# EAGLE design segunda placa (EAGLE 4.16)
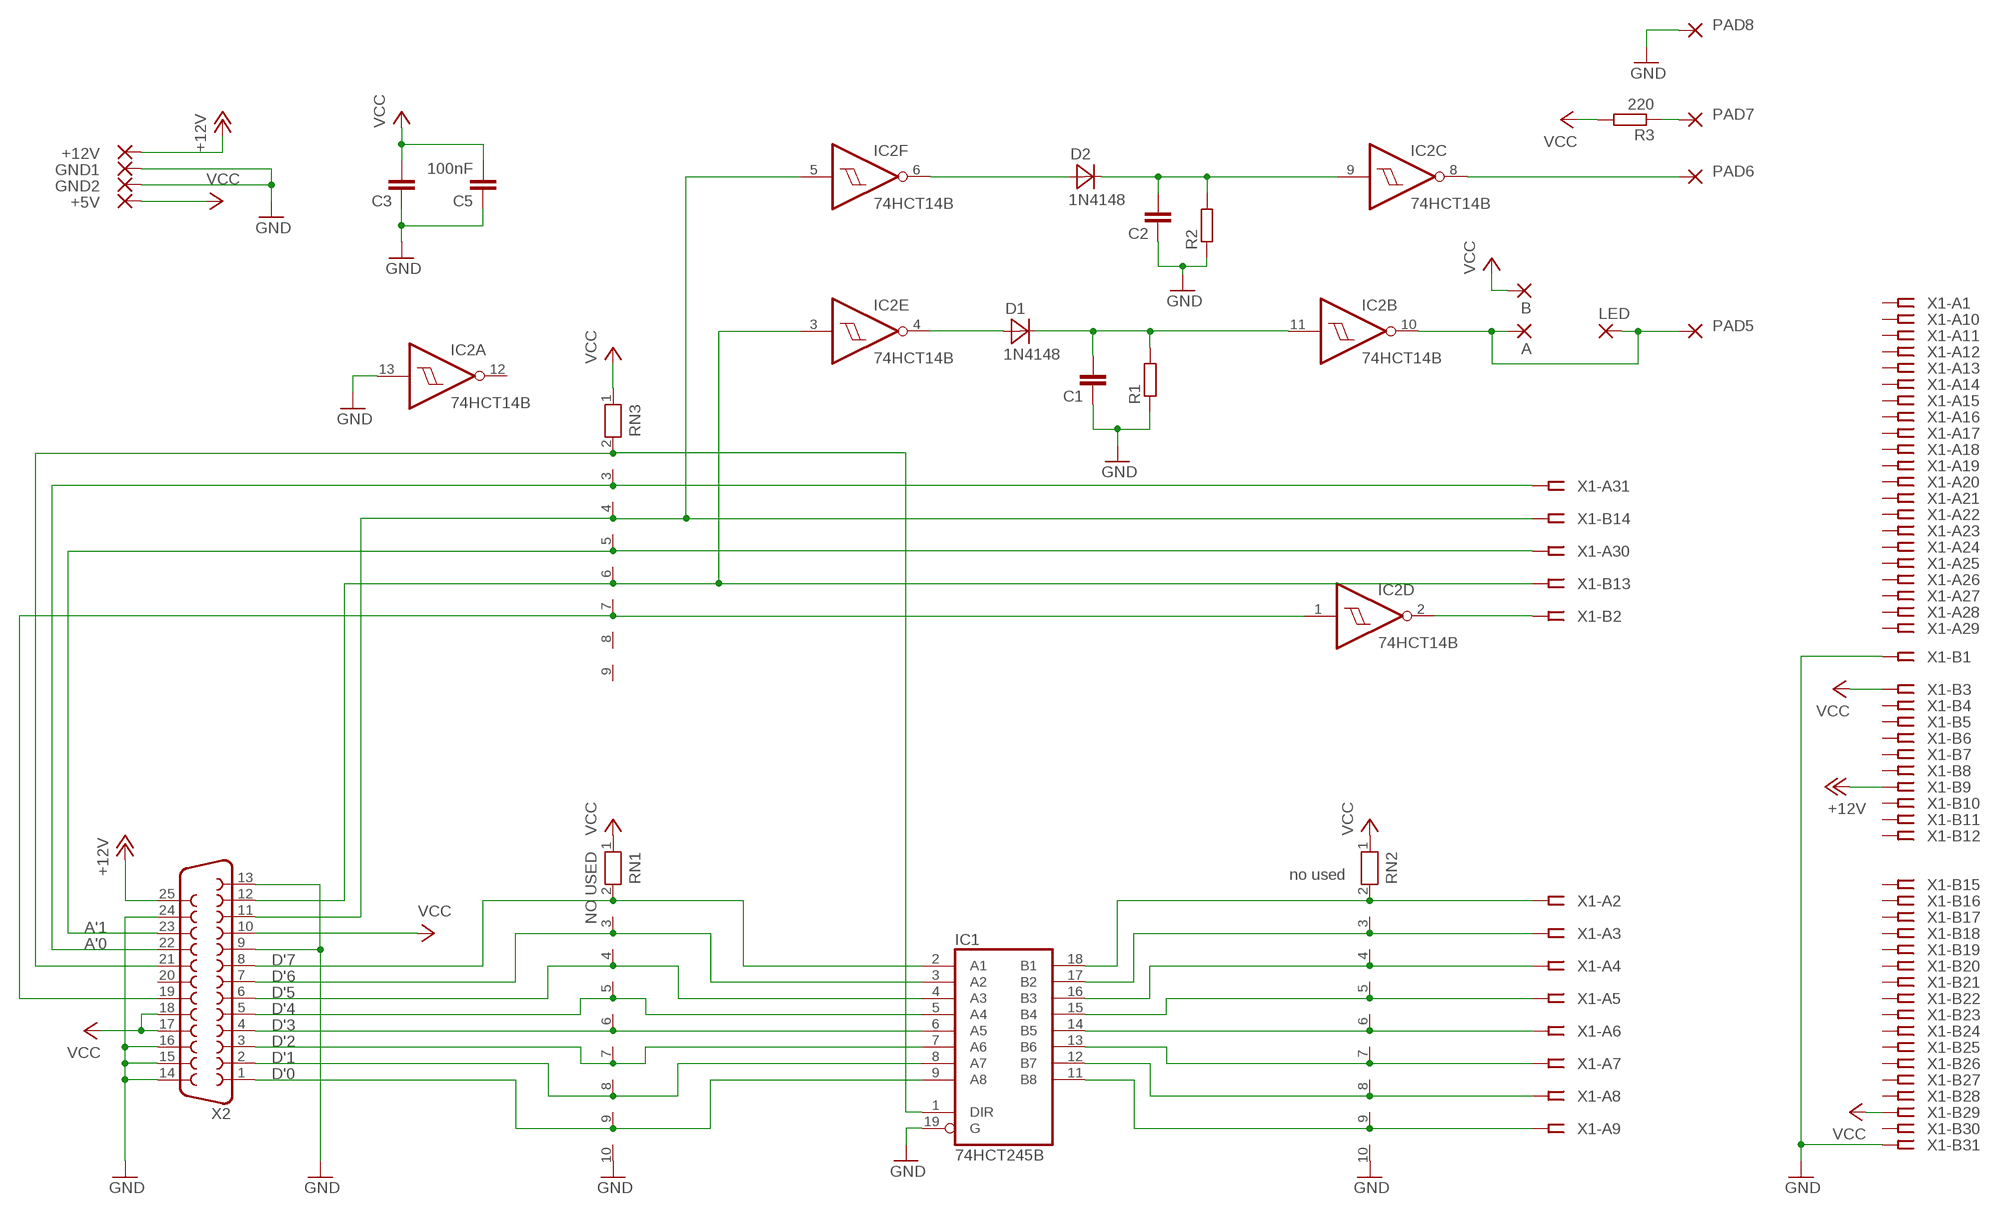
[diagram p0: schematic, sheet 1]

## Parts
+5V  1,6/0,9  [1,6/0,9]
+12V  1,6/0,9  [1,6/0,9]
A  SMD2  [SMD1,27-2,54]
B  SMD2  [SMD1,27-2,54]
C1  C-EU050-024X044  [C050-024X044]
C2  C-EU050-024X044  [C050-024X044]
C3  C-EU050-024X044  [C050-024X044]
C5  100nF  C-EU050-024X044  [C050-024X044]
D1  1N4148  DIODE-10/2  [D-10/2]
D2  1N4148  DIODE-10/2  [D-10/2]
GND1  1,6/0,9  [1,6/0,9]
GND2  1,6/0,9  [1,6/0,9]
IC1  74HCT245B  [DIL20-B]
IC2  74HCT14B  [DIL14-B]
LED  SMD2  [SMD1,27-2,54]
PAD5  1,6/0,9  [1,6/0,9]
PAD6  1,6/0,9  [1,6/0,9]
PAD7  1,6/0,9  [1,6/0,9]
PAD8  1,6/0,9  [1,6/0,9]
R1  R-EU_0207/10  [0207/10]
R2  R-EU_0207/10  [0207/10]
R3  220  R-EU_0207/10  [0207/10]
RN1  NO USED  RN091  [RN-101]
RN2  no used  RN091  [RN-101]
RN3  RN081  [RN-91]
X1  ISA-SLOT  [ISA-16]
X2  F25H  [F25H]

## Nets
+12V: +12V.1(P) X1.B9 X2.25
A'0: RN3.3 X1.A31 X2.22
A'1: RN3.5 X1.A30 X2.23
D'0: IC1.9(A8) RN1.9 X2.1
D'1: IC1.8(A7) RN1.8 X2.2
D'2: IC1.7(A6) RN1.7 X2.3
D'3: IC1.6(A5) RN1.6 X2.4
D'4: IC1.5(A4) RN1.5 X2.5
D'5: IC1.4(A3) RN1.4 X2.6
D'6: IC1.3(A2) RN1.3 X2.7
D'7: IC1.2(A1) RN1.2 X2.8
GND: C1.1 C2.1 C3.1 C5.1 GND1.1(P) GND2.1(P) IC1.19(G) IC2.13(A:I) PAD8.1(P) R1.1 R2.1 RN1.10 RN2.10 X1.B1 X1.B31 X2.9 X2.13 X2.14 X2.15 X2.16 X2.24
N$1: PAD7.1(P) R3.1
N$2: IC1.18(B1) RN2.2 X1.A2
N$3: IC1.17(B2) RN2.3 X1.A3
N$4: IC1.16(B3) RN2.4 X1.A4
N$5: IC1.15(B4) RN2.5 X1.A5
N$6: IC1.14(B5) RN2.6 X1.A6
N$7: IC1.13(B6) RN2.7 X1.A7
N$8: IC1.12(B7) RN2.8 X1.A8
N$9: IC1.11(B8) RN2.9 X1.A9
N$10: IC2.2(D:O) X1.B2
N$12: IC2.5(F:I) RN3.4 X1.B14 X2.11
N$13: IC2.1(D:I) RN3.7 X2.19
N$14: IC2.3(E:I) RN3.6 X1.B13 X2.12
N$16: IC1.1(DIR) RN3.2 X2.21
N$17: C2.2 D2.P$4(K) IC2.9(C:I) R2.2
N$18: C1.2 D1.P$4(K) IC2.11(B:I) R1.2
N$19: D1.P$3(A) IC2.4(E:O)
N$20: IC2.8(C:O) PAD6.1(P)
N$21: D2.P$3(A) IC2.6(F:O)
N$22: A.1(P) IC2.10(B:O) LED.1(P) PAD5.1(P)
VCC: +5V.1(P) B.1(P) C3.2 C5.2 R3.2 RN1.1 RN2.1 RN3.1 X1.B3 X1.B29 X2.10 X2.17 X2.18
Unconnected: IC2.12(A:O) RN3.8 RN3.9 X1.A1 X1.A10 X1.A11 X1.A12 X1.A13 X1.A14 X1.A15 X1.A16 X1.A17 X1.A18 X1.A19 X1.A20 X1.A21 X1.A22 X1.A23 X1.A24 X1.A25 X1.A26 X1.A27 X1.A28 X1.A29 X1.B4 X1.B5 X1.B6 X1.B7 X1.B8 X1.B10 X1.B11 X1.B12 X1.B15 X1.B16 X1.B17 X1.B18 X1.B19 X1.B20 X1.B21 X1.B22 X1.B23 X1.B24 X1.B25 X1.B26 X1.B27 X1.B28 X1.B30 X2.20

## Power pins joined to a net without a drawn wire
GND: IC1.10(GND) IC2.7(P:GND)
VCC: IC1.20(VCC) IC2.14(P:VCC)

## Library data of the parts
+5V +12V GND1 GND2 PAD5-PAD8 = wirepad:1,6/0,9: THROUGH-HOLE PAD
A B LED = wirepad:SMD2: SMD PAD
C1-C3 C5 = rcl:C-EU: CAPACITOR, European symbol
D1 D2 = discrete2:DIODE-10/2
IC1 = 74xx-eu2:74*245: Octal BUS TRANSCEIVER, 3-state
IC2 = 74xx-eu2:74*14: Hex schmitt trigger INVERTER
R1-R3 = rcl:R-EU_: RESISTOR, European symbol
RN1 RN2 = discrete2:RN09
RN3 = discrete2:RN08
X1 = con-pc2:ISA-SLOT: ISA SLOT
X2 = con-subd:F25: SUB-D

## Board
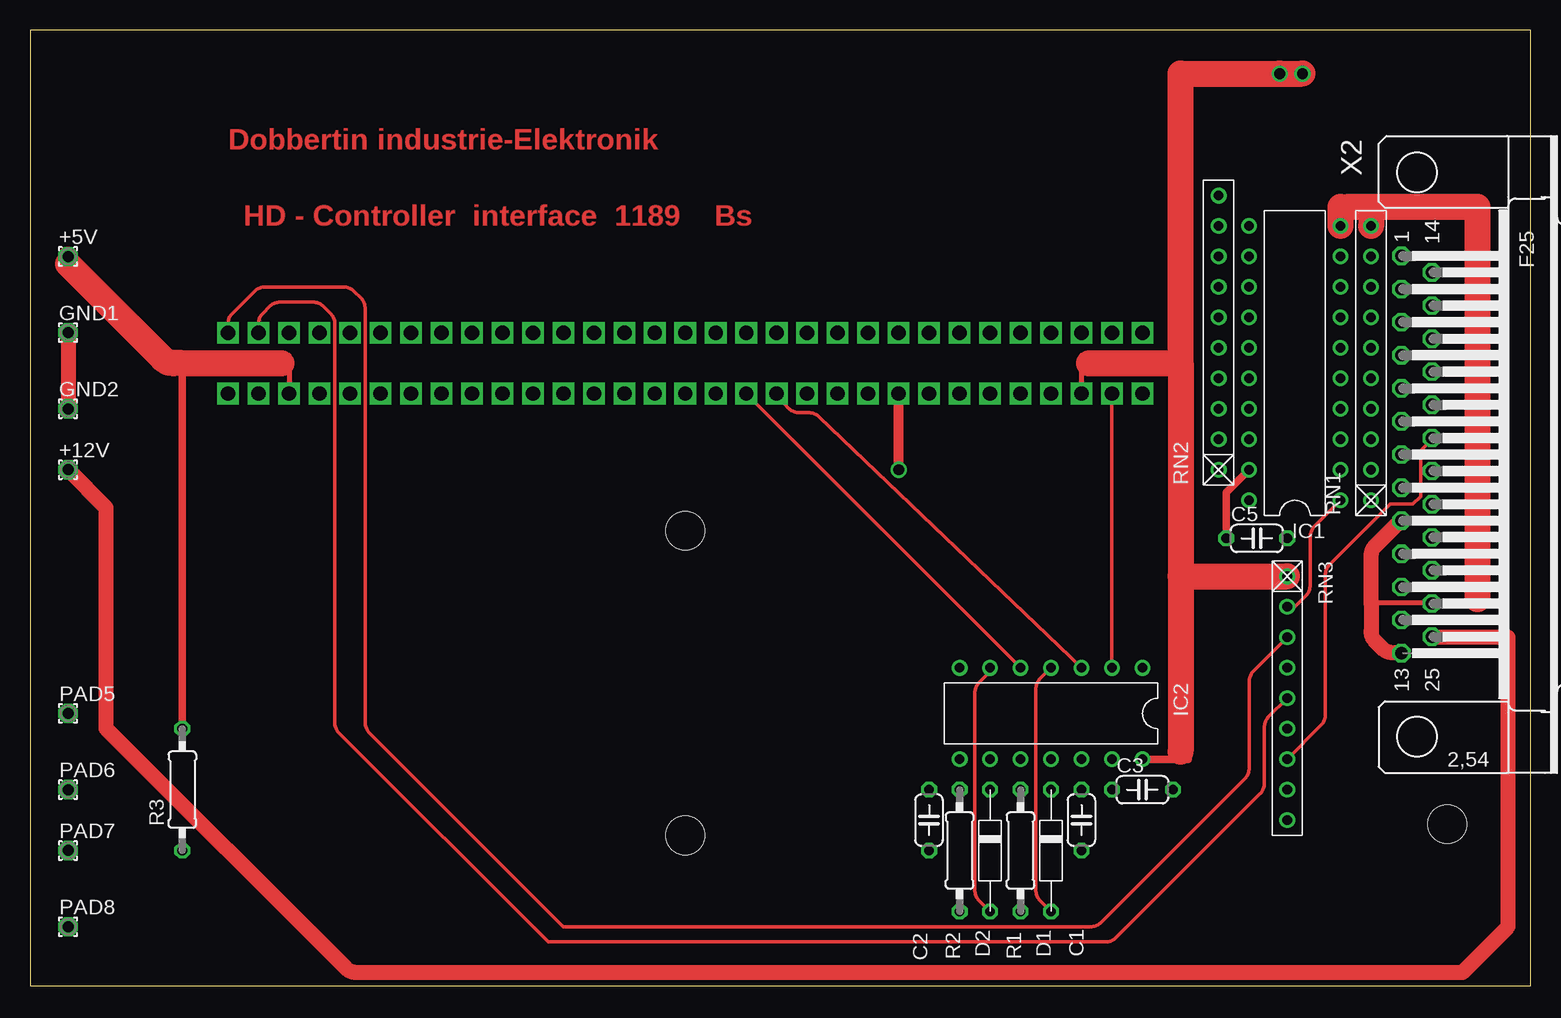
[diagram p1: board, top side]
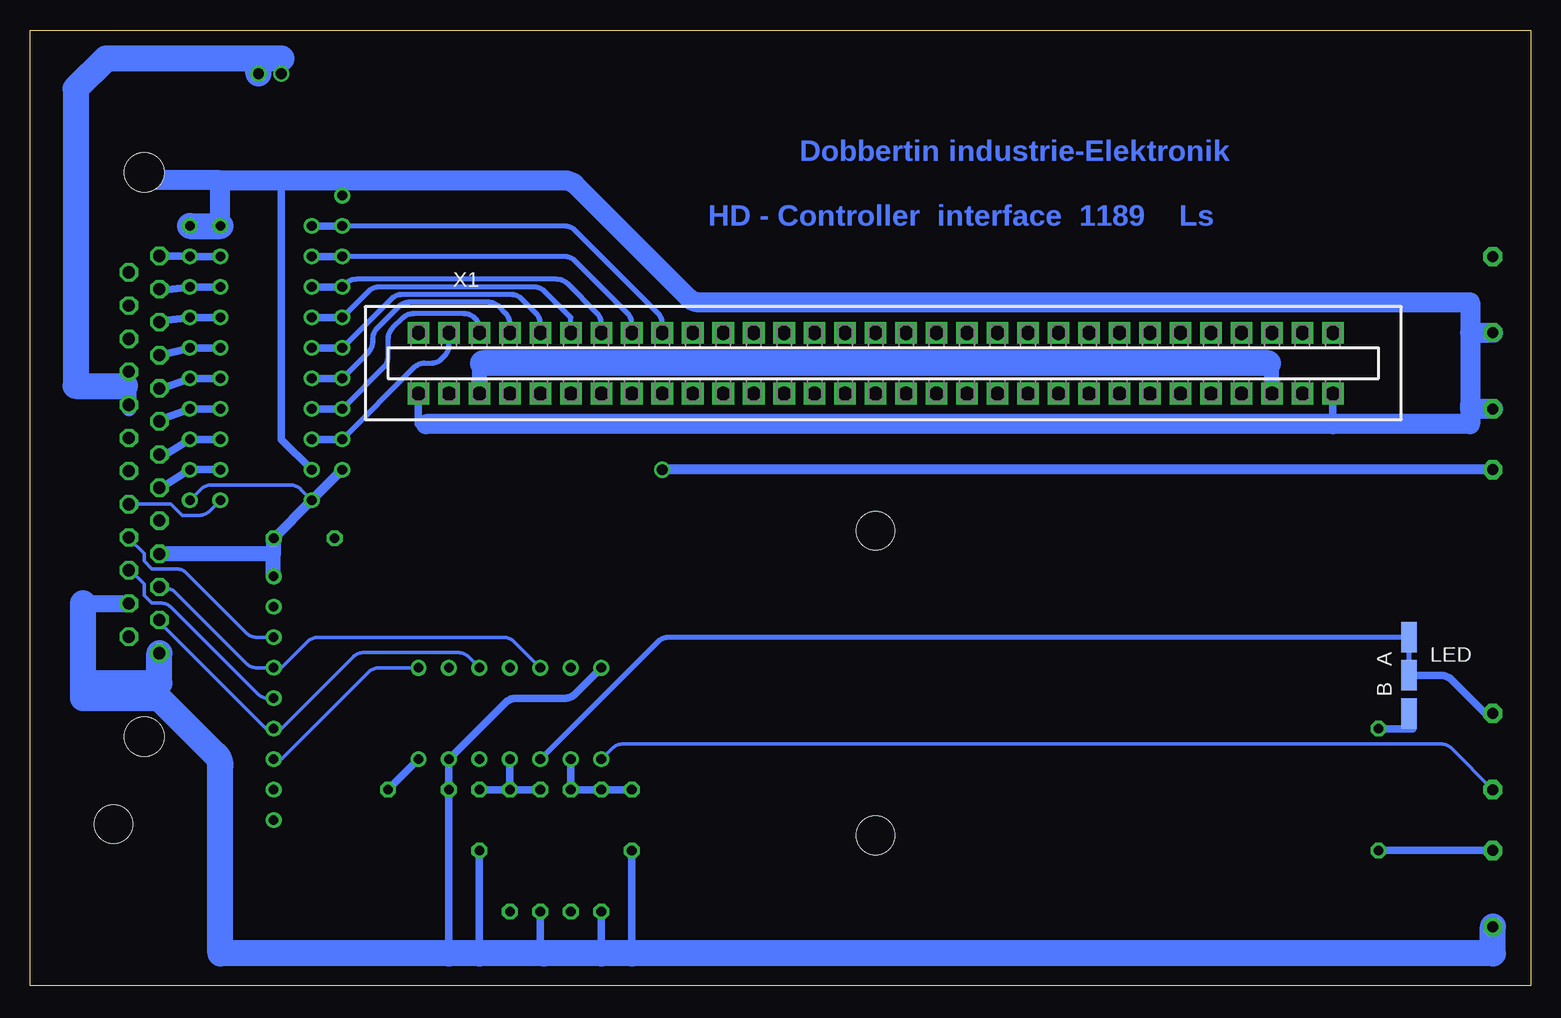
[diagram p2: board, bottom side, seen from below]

Size 125.08 x 79.68 mm. Coordinates in mm from the lower left corner, seen from the top.
Outline: 0,0 125.08,0 125.08,79.68 0,79.68 0,0
Copper layers (1*16): Top 0.035mm / dielectric 1.5mm / Bottom 0.035mm
Design rules "default": minimum track width 10mil, minimum drill 24mil, track to track 8mil, track to pad 8mil, pad to pad 8mil, via to via 8mil, smd to smd 8mil, copper to edge 40mil, drill to drill 8mil, minimum pad ring 10mil, minimum via ring 8mil, stop-mask expansion 4mil, vias tented up to drill 0mil, thermal gap 10mil
Holes 3.2 mm at 54.6,12.54 54.6,37.94 118.11,13.49

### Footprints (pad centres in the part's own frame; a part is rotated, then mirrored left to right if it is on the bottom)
1,6/0,9 = drill 0.914 pad 1.6 octagon: 1 0,0
SMD1,27-2,54 = smd 1.27 x 2.54: 1 0,0
C050-024X044 = drill 0.813 octagon: 1 -2.54,0; 2 2.54,0
D-10/2 = drill 0.813 octagon: P$3 -5.08,0; P$4 5.08,0
DIL20-B = drill 0.8 round: 1 -11.43,-3.81; 2 -8.89,-3.81; 3 -6.35,-3.81; 4 -3.81,-3.81; 5 -1.27,-3.81; 6 1.27,-3.81; 7 3.81,-3.81; 8 6.35,-3.81; 9 8.89,-3.81; 10 11.43,-3.81; 11 11.43,3.81; 12 8.89,3.81; 13 6.35,3.81; 14 3.81,3.81; 15 1.27,3.81; 16 -1.27,3.81; 17 -3.81,3.81; 18 -6.35,3.81; 19 -8.89,3.81; 20 -11.43,3.81
DIL14-B = drill 0.813 round: 1 -7.62,-3.81; 2 -5.08,-3.81; 3 -2.54,-3.81; 4 0,-3.81; 5 2.54,-3.81; 6 5.08,-3.81; 7 7.62,-3.81; 8 7.62,3.81; 9 5.08,3.81; 10 2.54,3.81; 11 0,3.81; 12 -2.54,3.81; 13 -5.08,3.81; 14 -7.62,3.81
0207/10 = drill 0.813 octagon: 1 -5.08,0; 2 5.08,0
RN-101 = drill 0.8 round: 1 -11.43,0; 2 -8.89,0; 3 -6.35,0; 4 -3.81,0; 5 -1.27,0; 6 1.27,0; 7 3.81,0; 8 6.35,0; 9 8.89,0; 10 11.43,0
RN-91 = drill 0.8 round: 1 -10.16,0; 2 -7.62,0; 3 -5.08,0; 4 -2.54,0; 5 0,0; 6 2.54,0; 7 5.08,0; 8 7.62,0; 9 10.16,0
ISA-16 = drill 1.2 pad 1.778 square: A1 81.28,-2.54; A2 78.74,-2.54; A3 76.2,-2.54; A4 73.66,-2.54; A5 71.12,-2.54; A6 68.58,-2.54; A7 66.04,-2.54; A8 63.5,-2.54; A9 60.96,-2.54; A10 58.42,-2.54; A11 55.88,-2.54; A12 53.34,-2.54; A13 50.8,-2.54; A14 48.26,-2.54; A15 45.72,-2.54; A16 43.18,-2.54; A17 40.64,-2.54; A18 38.1,-2.54; A19 35.56,-2.54; A20 33.02,-2.54; A21 30.48,-2.54; A22 27.94,-2.54; A23 25.4,-2.54; A24 22.86,-2.54; A25 20.32,-2.54; A26 17.78,-2.54; A27 15.24,-2.54; A28 12.7,-2.54; A29 10.16,-2.54; A30 7.62,-2.54; A31 5.08,-2.54; B1 81.28,2.54; B2 78.74,2.54; B3 76.2,2.54; B4 73.66,2.54; B5 71.12,2.54; B6 68.58,2.54; B7 66.04,2.54; B8 63.5,2.54; B9 60.96,2.54; B10 58.42,2.54; B11 55.88,2.54; B12 53.34,2.54; B13 50.8,2.54; B14 48.26,2.54; B15 45.72,2.54; B16 43.18,2.54; B17 40.64,2.54; B18 38.1,2.54; B19 35.56,2.54; B20 33.02,2.54; B21 30.48,2.54; B22 27.94,2.54; B23 25.4,2.54; B24 22.86,2.54; B25 20.32,2.54; B26 17.78,2.54; B27 15.24,2.54; B28 12.7,2.54; B29 10.16,2.54; B30 7.62,2.54; B31 5.08,2.54
F25H = drill 1.016 octagon: 1 -16.561,-1.27; 2 -13.792,-1.27; 3 -11.049,-1.27; 4 -8.28,-1.27; 5 -5.512,-1.27; 6 -2.769,-1.27; 7 0,-1.27; 8 2.769,-1.27; 9 5.512,-1.27; 10 8.28,-1.27; 11 11.049,-1.27; 12 13.792,-1.27; 13 16.561,-1.27; 14 -15.189,1.27; 15 -12.421,1.27; 16 -9.652,1.27; 17 -6.909,1.27; 18 -4.14,1.27; 19 -1.372,1.27; 20 1.372,1.27; 21 4.14,1.27; 22 6.909,1.27; 23 9.652,1.27; 24 12.421,1.27; 25 15.189,1.27 | hole 3.302: -23.52,0; 23.52,0

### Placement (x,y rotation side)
+5V  3.17,60.8 0 top
+12V  3.17,43.02 0 top
A  10.15,29.05 0 bottom
B  10.15,22.7 0 bottom
C1  87.62,13.81 90 top
C2  74.93,13.81 90 top
C3  92.7,16.35 0 top
C5  102.23,37.3 0 top
D1  85.09,11.27 90 top
D2  80.01,11.27 90 top
GND1  3.17,54.45 0 top
GND2  3.17,48.09 0 top
IC1  105.41,51.91 90 top
IC2  85.09,22.7 180 top
LED  10.15,25.87 0 bottom
PAD5  3.17,22.7 0 top
PAD6  3.17,16.35 0 top
PAD7  3.17,11.27 0 top
PAD8  3.17,4.92 0 top
R1  82.55,11.27 90 top
R2  77.47,11.27 90 top
R3  12.69,16.35 90 top
RN1  111.76,51.91 90 top
RN2  99.06,54.45 90 top
RN3  104.77,23.96 270 top
X1  11.42,51.91 180 bottom
X2  115.56,44.29 270 top

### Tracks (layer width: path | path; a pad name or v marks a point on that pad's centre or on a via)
+12V  (via drill 0.9)
  Top 0.813: v72.39,43.02 X1.B9
  Top 1.27: +12V.1 6.34,39.84 6.34,21.43 26.29,1.48 arc45 27.19,1.1 119.38,1.1 123.19,4.92 123.19,29.05 116.84,29.05 X2.25
  Bottom 0.813: +12V.1 v72.39,43.02
A'0
  Top 0.305: X1.A31 16.51,55.19 arc-45 16.88,56.09 18.67,57.88 arc-45 19.57,58.26 26.14,58.26 arc-45 27.04,57.88 27.56,57.36 arc-45 27.94,56.46 27.94,21.95 arc45 28.31,21.05 44.45,4.92 88.37,4.92 arc45 89.27,5.29 101.22,17.24 arc45 101.59,18.14 101.59,25.34 arc-45 101.97,26.24 RN3.3
  Bottom 0.305: X2.22 116.84,37.3 115.56,36.03 115.56,35.4 114.93,34.76 112.92,34.76 arc45 112.02,34.39 107.05,29.42 arc-45 106.15,29.05 RN3.3
A'1
  Top 0.305: X1.A30 19.05,55.19 arc-45 19.42,56.09 19.94,56.61 arc-45 20.84,56.98 23.6,56.98 arc-45 24.5,56.61 25.02,56.09 arc-45 25.39,55.19 25.39,21.95 arc45 25.77,21.05 43.17,3.65 89.64,3.65 arc45 90.54,4.02 102.49,15.97 arc45 102.87,16.87 102.87,21.53 arc-45 103.24,22.43 RN3.5
  Bottom 0.305: X2.23 116.71,34.63 115.56,33.49 115.56,32.54 114.93,31.9 114.19,31.9 arc45 113.29,31.53 106.09,24.34 arc-45 105.2,23.96 RN3.5
D'0
  Bottom 0.61: IC1.9 RN1.9 111.81,60.85 X2.1
D'1
  Bottom 0.61: IC1.8 RN1.8 114.3,57.94 X2.2
D'2
  Bottom 0.61: IC1.7 RN1.7 114.3,55.4 X2.3
D'3
  Bottom 0.61: IC1.6 RN1.6 114.3,52.54 X2.4
D'4
  Bottom 0.61: IC1.5 RN1.5 114.3,49.68 X2.5
D'5
  Bottom 0.61: IC1.4 RN1.4 114.3,47.14 X2.6
D'6
  Bottom 0.61: IC1.3 RN1.3 114.3,43.97 X2.7
D'7
  Bottom 0.61: IC1.2 RN1.2 114.3,41.43 X2.8
GND
  Top 0.406: 114.3,38.89 120.65,38.89 | 116.84,31.9 111.76,31.9
  Top 0.61: C5.1 99.69,41.11 IC1.19 | X2.24 116.84,31.9 120.65,31.9 120.65,32.22 | 120.65,59.52 120.33,59.52 120.28,59.47 X2.14 | X2.15 120.61,56.71 120.65,56.67 | X2.16 120.45,53.94 120.65,54.13
  Top 1.27: 114.3,27.78 113.55,27.78 arc-45 112.65,28.15 112.13,28.67 arc-45 111.76,29.57 111.76,31.9 111.76,35.82 arc-45 112.13,36.72 114.3,38.89 X2.9 | 109.85,64.92 109.22,64.92 | GND1.1 GND2.1
  Top 2.184: 120.65,32.22 120.65,38.89 120.65,54.13 120.65,56.67 120.65,59.52 120.65,64.92 111.76,64.92 | 111.76,64.92 109.85,64.92 | IC1.10 109.22,64.92 | 111.76,64.92 RN1.10
  Bottom 0.61: IC2.13 85.46,23.59 arc45 84.56,23.96 80.53,23.96 arc-45 79.63,24.34 IC2.7 | 90.17,16.03 C3.1 IC2.13 | 90.17,2.69 IC2.13 | IC1.19 104.14,45.55 104.14,67.14 | 92.07,46.83 92.7,46.83 X1.B1 | 16.51,46.83 X1.B31 | 74.93,2.69 C2.1 | 77.47,2.38 77.47,2.69 R2.1 | R1.1 82.55,3.01 82.23,2.69 | 87.62,2.69 C1.1 | 99.06,67.14 RN2.10
  Bottom 1.422: X2.24 120.61,31.86 120.65,31.9
  Bottom 1.676: 5.08,48.41 5.08,48.09 GND2.1 | 5.08,54.45 5.08,48.41 | 5.08,54.45 5.08,56.98 69.32,56.98 arc45 70.22,57.36 79.63,66.77 arc-45 80.53,67.14 99.06,67.14 104.14,67.14 109.22,67.14 | 5.08,54.45 GND1.1 | 5.08,48.41 5.08,46.83 16.51,46.83 92.07,46.83 | 109.22,67.14 115.56,67.14 | IC1.10 109.22,67.14
  Bottom 2.184: 120.65,25.23 120.65,23.96 114.3,23.96 109.59,19.26 arc45 109.22,18.36 109.22,2.69 90.17,2.69 87.62,2.69 82.23,2.69 77.47,2.69 74.93,2.69 3.17,2.69 PAD8.1 | 120.65,25.23 120.65,31.9 | X2.13 114.3,25.23 120.65,25.23 | RN1.10 IC1.10
N$1
  Bottom 0.61: PAD7.1 R3.1
N$2
  Bottom 0.406: RN2.2 93.08,51.53 arc45 92.18,51.91 91.64,51.91 arc-45 90.75,52.28 90.54,52.49 arc-45 90.17,53.38 X1.A2
  Bottom 0.61: RN2.2 IC1.18
N$3
  Bottom 0.406: RN2.3 98.74,48.09 98.74,48.41 95.62,51.53 arc-45 95.25,52.43 95.25,53.92 arc45 94.87,54.82 94.03,55.66 arc45 93.13,56.03 88.9,56.03 arc90 87.62,54.76 X1.A3
  Bottom 0.61: RN2.3 IC1.17
N$4
  Bottom 0.406: RN2.4 96.89,52.8 arc-45 96.52,53.7 96.52,53.92 arc45 96.14,54.82 94.35,56.61 arc45 93.45,56.98 86.88,56.98 arc45 85.98,56.61 85.46,56.09 arc45 85.09,55.19 X1.A4
  Bottom 0.61: RN2.4 IC1.16
N$5
  Bottom 0.406: RN2.5 94.98,57.25 arc45 94.08,57.62 84.98,57.62 arc45 84.08,57.25 82.92,56.09 arc45 82.55,55.19 X1.A5
  Bottom 0.61: RN2.5 IC1.15
N$6
  Bottom 0.406: RN2.6 96.89,57.88 arc45 95.99,58.26 83.07,58.26 arc45 82.17,57.88 80.01,55.72 X1.A6
  Bottom 0.61: RN2.6 IC1.14
N$7
  Bottom 0.406: RN2.7 98.79,58.52 arc45 97.89,58.89 81.17,58.89 arc45 80.27,58.52 77.84,56.09 arc45 77.47,55.19 X1.A7
  Bottom 0.61: RN2.7 IC1.13
N$8
  Bottom 0.406: RN2.8 80.53,60.8 arc45 79.63,60.42 75.3,56.09 arc45 74.93,55.19 X1.A8
  Bottom 0.61: RN2.8 IC1.12
N$9
  Bottom 0.406: RN2.9 80.53,63.34 arc45 79.63,62.96 72.76,56.09 arc45 72.39,55.19 X1.A9
  Bottom 0.61: RN2.9 IC1.11
N$10
  Top 0.305: IC2.2 X1.B2
N$12
  Top 0.305: X1.B14 IC2.5
  Bottom 0.305: IC2.5 84.71,28.67 arc-45 85.61,29.05 101.07,29.05 arc-45 101.97,28.67 104.14,26.51 RN3.4 106.15,26.51 arc45 107.05,26.88 112.97,32.8 arc-45 113.87,33.17 114.3,33.17 X2.11
N$13
  Top 0.305: X2.19 116.84,45.55 115.88,44.6 115.88,40.79 115.25,40.16 113.34,40.16 108.32,35.13 arc45 107.95,34.23 107.95,22.59 arc-45 107.57,21.69 RN3.7
  Bottom 0.305: IC2.1 95.99,26.51 arc-45 96.89,26.13 104.14,18.89 RN3.7
N$14
  Top 0.305: X1.B13 63.11,48.25 arc51 64.11,47.78 64.89,47.78 arc-44 65.77,47.43 IC2.3
  Bottom 0.305: IC2.3 88.52,27.4 arc-45 89.42,27.78 97.26,27.78 arc-45 98.16,27.4 104.14,21.43 RN3.6 105.41,21.43 114.3,30.32 X2.12
N$16
  Top 0.305: RN3.2 105.41,31.59 106.3,32.48 arc45 106.68,33.38 106.68,37.41 arc-45 107.05,38.31 IC1.1
  Bottom 0.305: IC1.1 110.11,39.58 arc45 111.01,39.2 112.39,39.2 113.34,40.16 116.84,40.16 X2.21
N$17
  Bottom 0.61: C2.2 R2.2 D2.P$4 IC2.9
N$18
  Bottom 0.61: D1.P$4 85.4,16.35 | R1.2 D1.P$4 | D1.P$4 C1.2 | D1.P$4 IC2.11
N$19
  Top 0.305: D1.P$3 84.19,7.08 arc-45 83.81,7.98 83.81,24.71 arc-45 84.19,25.61 IC2.4
N$20
  Bottom 0.305: IC2.8 76.57,19.78 arc45 75.67,20.16 7.51,20.16 arc45 6.61,19.78 PAD6.1
N$21
  Top 0.305: IC2.6 80.32,26.51 79.11,25.29 arc45 78.73,24.39 78.73,7.98 arc45 79.11,7.08 D2.P$3
N$22
  Bottom 0.406: IC2.10 72.76,28.67 arc45 71.86,29.05 A.1 LED.1
  Bottom 0.61: PAD5.1 3.81,22.7 6.61,25.5 arc-45 7.51,25.87 LED.1
VCC  (via drill 0.9)
  Top 0.406: 96.52,18.89 96.52,19.52 95.88,19.52 95.25,19.52 95.25,18.89 | 20.95,51.91 20.95,52.54 21.59,52.54 X1.B29 | 87.62,51.91 87.62,52.54 | 87.62,51.91 88.26,51.91 | X1.B3 87.62,51.91
  Top 0.61: R3.2 12.69,51.91 | IC2.14 95.25,18.89 95.88,18.89 | 95.88,18.89 96.52,18.89 | 95.88,19.52 95.88,18.89
  Top 1.676: 3.17,60.16 +5V.1
  Top 2.184: 3.17,60.16 11.05,52.28 arc45 11.95,51.91 12.69,51.91 20.95,51.91 | 95.88,34.12 95.88,19.52 | 95.88,51.91 95.88,34.12 | 95.88,51.91 95.88,76.03 v104.14,76.03 v106.04,76.03 | 88.26,51.91 95.88,51.91 | 95.88,34.12 RN3.1
  Bottom 0.305: RN1.1 110.86,41.37 arc45 109.96,41.74 103.39,41.74 arc45 102.49,41.37 IC1.20
  Bottom 0.61: IC2.14 C3.2 | 10.15,21.43 R3.2 | 9.84,21.43 10.15,21.43 | 10.15,21.43 B.1
  Bottom 0.813: C5.2 IC1.20 RN2.1
  Bottom 1.27: 116.84,48.09 X2.18 116.84,50 117.15,50 116.84,49.68 X2.17 | v104.14,76.03 104.14,77.3 | 104.8,36.01 X2.10 | 104.8,36.01 104.77,36.03 C5.2 | 104.8,36.01 104.8,34.15 RN3.1 | X1.B29 21.59,51.91 21.9,51.91 | 87.31,51.91 87.62,51.91 X1.B3
  Bottom 2.184: 117.15,50 121.28,50 121.28,74.77 118.74,77.3 106.04,77.3 | 104.14,77.3 106.04,77.3 | v106.04,76.03 106.04,77.3 | 21.9,51.91 87.31,51.91

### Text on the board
Top: Dobbertin industrie-Elektronik | HD - Controller interface 1189 Bs
Bottom: Dobbertin industrie-Elektronik | HD - Controller interface 1189 Ls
